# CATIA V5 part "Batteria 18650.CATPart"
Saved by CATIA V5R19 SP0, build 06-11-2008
Part number: Batteria 18650
Bounding box of the stored display mesh (mm): x -9.07 to 9.07, y -9.004 to 9.004, z 0 to 61
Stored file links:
  C:\Users\sisca\Desktop\HELTEC_CASE\Batteria 18650.CATPart
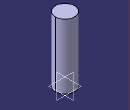
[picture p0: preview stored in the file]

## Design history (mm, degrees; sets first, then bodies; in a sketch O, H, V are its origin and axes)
Body1 (main body)
  Sketch1 on xy-plane, origin (0, 0, 0), H (1, 0, 0), V (0, 1, 0)
    circle A1 centre (0, 0) radius 9.07
    radius A1 = 9.07
  Pad1: profile Sketch1, direction (0, 0, 1), length 61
